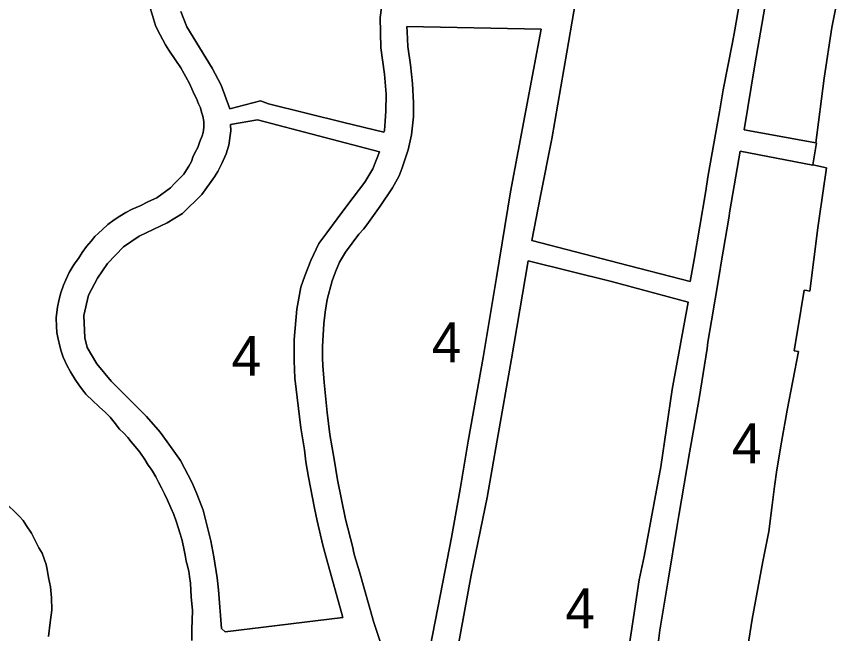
# Model space of a CAD drawing. Extents: x 598968 to 613553, y 4409678 to 4430833.
# Drawn here: x 610904.6 to 611152.7, y 4416094 to 4416279.7 of the extents above; entities that cross this region are included whole.
import ezdxf

# ---------------------------------------------------------------- set-up
doc = ezdxf.new("R2010")
doc.units = 0
doc.layers.add('1', color=7, linetype='Continuous')
doc.layers.add('ZONA 4. CASES UNIFAMILIRAS AÏLLADES EN PARCEL.LES', color=7, linetype='Continuous')

msp = doc.modelspace()

# ---------------------------------------------------------------- linework, layer by layer
at = {"layer": '1'}
for points in [[(611122.1465, 4416283.2261), (611120.8443, 4416275.6965), (611120.1666, 4416271.9363), (611117.4167, 4416257.6564), (611116.2567, 4416251.0565), (611112.8968, 4416231.9567), (611112.0195, 4416226.6664), (611108.6869, 4416206.517), (611107.4169, 4416199.977), (611086.0378, 4416205.4807), (611059.7635, 4416212.2445), (611062.3773, 4416225.6928), (611065.8373, 4416242.8526), (611070.3271, 4416269.0224), (611074.477, 4416293.5821)], [(611152.7081, 4416289.6021), (611150.0762, 4416276.3668), (611147.8011, 4416261.1727), (611145.2963, 4416241.7072), (611145.5123, 4416241.6598), (611144.3636, 4416235.0255), (611148.4575, 4416234.1782), (611148.462, 4416234.1773), (611146.2797, 4416218.9008), (611145.8798, 4416216.1015), (611143.4764, 4416197.0747), (611142.5332, 4416197.2156), (611141.7364, 4416197.3346), (611139.8278, 4416185.7171), (611138.7449, 4416179.1258), (611138.7365, 4416179.0748), (611140.0573, 4416178.8635), (611140.0635, 4416178.8624), (611136.6245, 4416161.1893), (611134.9487, 4416151.6049), (611133.4887, 4416143.2279), (611132.8409, 4416138.1859), (611132.1202, 4416132.576), (611131.1048, 4416124.6728), (611129.2758, 4416115.6243), (611126.1216, 4416098.3258), (611124.7964, 4416090.0759)], [(611015.1347, 4416286.7958), (611014.1521, 4416279.4314), (611014.1528, 4416279.4029), (611014.1521, 4416279.3983), (611014.3487, 4416270.2895), (611015.4516, 4416262.3707), (611015.9224, 4416256.3121), (611015.8442, 4416251.2356), (611015.6477, 4416248.2124), (611015.3726, 4416245.3855), (611015.1979, 4416244.8948), (611003.1665, 4416247.848), (610980.4483, 4416253.4441), (610978.1184, 4416254.304), (610968.8635, 4416251.8889), (610966.2785, 4416259.0637), (610963.5385, 4416264.2136), (610955.9187, 4416276.5833), (610954.1386, 4416281.2632)], [(610944.9886, 4416282.0114), (610946.5088, 4416276.9931), (610947.037, 4416275.6868), (610947.8401, 4416274.1826), (610949.528, 4416271.1649), (610950.5117, 4416269.5603), (610952.5788, 4416266.4934), (610954.0882, 4416264.2951), (610955.5686, 4416261.5235), (610956.6687, 4416259.5236), (610957.4232, 4416257.9484), (610958.1259, 4416256.3839), (610958.8186, 4416255.0037), (610959.4535, 4416253.4221), (610960.0286, 4416252.1737), (610960.3486, 4416250.9037), (610960.6992, 4416249.7056), (610960.9802, 4416248.0608), (610960.9802, 4416248.0278), (610960.9802, 4416246.2757), (610960.7995, 4416244.7646), (610960.5186, 4416243.7938), (610959.7957, 4416242.0768), (610959.1923, 4416240.322), (610958.2688, 4416238.6371), (610957.7447, 4416237.4055), (610957.3187, 4416236.0439), (610956.5187, 4416234.6439), (610955.8487, 4416233.5939), (610955.0187, 4416232.2939), (610953.6387, 4416230.8839), (610952.2888, 4416229.5539), (610950.9627, 4416228.0904), (610946.8549, 4416225.1727), (610944.3817, 4416224.0145), (610941.8389, 4416222.6938), (610939.4983, 4416221.6852), (610937.5459, 4416220.7017), (610935.7648, 4416219.6033), (610934.0291, 4416218.4637), (610932.1391, 4416217.1437), (610930.4919, 4416215.6001), (610929.3155, 4416214.5194), (610928.2291, 4416213.5337), (610927.1292, 4416212.0737), (610925.6692, 4416210.4337), (610924.3532, 4416208.6325), (610923.2703, 4416206.8478), (610922.3324, 4416205.5315), (610921.6992, 4416204.7037), (610920.5212, 4416202.5992), (610919.4605, 4416200.4798), (610918.7393, 4416198.8437), (610917.952, 4416196.5591), (610917.4601, 4416194.5912), (610916.9602, 4416192.2237), (610916.7395, 4416190.7002), (610916.6191, 4416189.0163), (610916.6191, 4416188.9833), (610916.6199, 4416186.3959), (610916.6199, 4416186.3628), (610916.8082, 4416184.6291), (610917.0909, 4416183.0993), (610917.761, 4416180.1011), (610918.029, 4416178.9707), (610918.6448, 4416177.2014), (610919.737, 4416174.787), (610920.8794, 4416172.7505), (610922.2802, 4416170.4248), (610923.6399, 4416168.4813), (610924.8636, 4416166.8281), (610925.4997, 4416166.0589), (610925.9461, 4416165.613), (610927.3319, 4416164.2808), (610929.6592, 4416162.1014), (610931.3492, 4416160.5615), (610932.8469, 4416159.0586), (610934.0292, 4416157.6215), (610935.6572, 4416155.5236), (610936.9397, 4416154.298), (610938.1106, 4416153.0167), (610939.1835, 4416151.6825), (610940.3211, 4416150.2562), (610941.7264, 4416148.5627), (610943.2291, 4416146.3319), (610944.3091, 4416144.6419), (610945.0182, 4416143.7515), (610945.6032, 4416142.7907), (610946.5892, 4416141.082), (610947.3778, 4416139.5013), (610948.2795, 4416137.7842), (610949.1963, 4416135.9894), (610950.0984, 4416134.1272), (610951.1268, 4416131.7765), (610951.9728, 4416129.8295), (610952.8054, 4416127.5168), (610953.8905, 4416123.9502), (610954.5105, 4416121.9374), (610955.1454, 4416119.0299), (610955.3568, 4416117.5801), (610955.7515, 4416115.7867), (610955.9347, 4416115.0266), (610956.4705, 4416112.7539), (610956.7382, 4416111.1351), (610956.9927, 4416109.1003), (610957.2608, 4416104.9844), (610957.5708, 4416100.9311), (610957.4469, 4416095.2132), (610957.3662, 4416091.8164)], [(611097.8675, 4416091.7255), (611098.3473, 4416094.9907), (611100.9371, 4416110.6152), (611103.407, 4416125.915), (611104.027, 4416129.525), (611107.287, 4416148.3547), (611110.1069, 4416164.7546), (611112.5245, 4416179.7333), (611112.7206, 4416181.6279), (611113.8927, 4416188.1256), (611115.9988, 4416200.5446), (611117.0653, 4416207.3976), (611117.385, 4416209.0743), (611119.091, 4416219.0271), (611119.4107, 4416221.183), (611122.5031, 4416239.1318), (611144.3404, 4416234.964), (611144.3636, 4416235.0255), (611145.5123, 4416241.6598), (611145.2963, 4416241.7072), (611123.6561, 4416245.6391), (611126.9333, 4416265.1438), (611129.931, 4416282.5068)], [(611016.3828, 4416084.7543), (611012.2518, 4416097.2903), (611007.8794, 4416112.4803), (611006.3971, 4416117.4883), (611006.0904, 4416118.7905), (611005.8348, 4416119.8373), (611003.6918, 4416128.3804), (611001.2197, 4416140.2281), (611000.2379, 4416146.448), (610999.6927, 4416149.8759), (610998.966, 4416153.9056), (610998.1304, 4416160.4855), (610997.2222, 4416169.5721), (610996.8231, 4416174.6028), (610996.7867, 4416176.781), (610996.7146, 4416180.3867), (610996.7142, 4416180.4114), (610997.1147, 4416187.2423), (610997.5523, 4416190.6726), (610998.1721, 4416194.5333), (610999.6983, 4416200.1241), (611000.7157, 4416202.883), (611001.9189, 4416205.766), (611003.6994, 4416208.7793), (611007.6645, 4416214.1633), (611009.1089, 4416215.6583), (611010.078, 4416216.9551), (611014.128, 4416222.6351), (611017.8029, 4416228.0951), (611019.8144, 4416231.7556), (611020.7335, 4416234.143), (611022.5751, 4416239.5291), (611023.5861, 4416244.1204), (611024.1375, 4416249.492), (611024.1395, 4416253.7395), (611024.1395, 4416253.7725), (611023.8658, 4416259.5739), (611023.2259, 4416265.1419), (611022.4906, 4416270.6972), (611022.2148, 4416275.0587), (611022.1699, 4416276.7255), (611062.5626, 4416275.9507), (611053.3833, 4416226.9164), (611049.0954, 4416201.1785), (611045.1718, 4416177.1058), (611040.5813, 4416151.8625), (611038.2042, 4416137.3883), (611035.638, 4416122.8969), (611032.945, 4416109.3755), (611029.1361, 4416089.805)], [(611037.3188, 4416088.5158), (611041.4857, 4416111.5126), (611046.3477, 4416134.8939), (611049.3377, 4416152.1236), (611053.6075, 4416176.7034), (611057.7974, 4416200.8531), (611058.7175, 4416206.1531), (611083.7571, 4416199.9636), (611106.8796, 4416193.7418), (611102.0267, 4416167.4123), (611098.657, 4416144.1277), (611094.4232, 4416121.4989), (611093.5561, 4416117.1088), (611092.1134, 4416110.1426), (611090.38, 4416098.7781), (611088.7436, 4416088.193)], [(610914.2934, 4416093.0549), (610914.7818, 4416097.289), (610915.2483, 4416101.0234), (610915.2474, 4416101.0494), (610915.2483, 4416101.0565), (610915.1227, 4416104.7186), (610914.8355, 4416108.0579), (610914.2436, 4416110.8711), (610913.8479, 4416113.2442), (610913.543, 4416114.6955), (610912.3222, 4416118.145), (610911.3896, 4416119.7934), (610909.1481, 4416124.1543), (610907.655, 4416126.342), (610906.6517, 4416127.946), (610905.5334, 4416129.235), (610900.8315, 4416133.8465)]]:
    msp.add_lwpolyline(points, dxfattribs=at)
msp.add_lwpolyline([(611002.8316, 4416098.7918), (610967.4717, 4416094.4961), (610966.3677, 4416095.5051), (610965.4269, 4416107.103), (610965.0036, 4416110.7433), (610964.0632, 4416117.0631), (610963.17, 4416121.861), (610960.7877, 4416131.0548), (610958.8942, 4416135.9918), (610957.5062, 4416139.2727), (610953.9631, 4416146.039), (610949.9698, 4416151.704), (610947.8535, 4416154.6152), (610943.7223, 4416159.3408), (610942.0877, 4416161.0234), (610933.1102, 4416169.9663), (610928.7871, 4416175.1939), (610925.952, 4416180.0798), (610925.1556, 4416182.9363), (610924.864, 4416189.7219), (610924.8628, 4416189.75), (610926.3502, 4416195.8591), (610929.0423, 4416200.9614), (610932.0094, 4416205.3125), (610936.88, 4416210.4141), (610941.5501, 4416213.5631), (610949.9472, 4416217.612), (610954.6201, 4416220.4397), (610960.3839, 4416226.1369), (610964.2491, 4416231.412), (610965.2016, 4416233.0937), (610966.4386, 4416235.474), (610967.774, 4416238.4233), (610968.5191, 4416240.9716), (610969.1199, 4416245.2817), (610969.099, 4416247.1694), (610977.1573, 4416248.5794), (611013.9124, 4416238.9693), (611011.948, 4416233.8649), (611009.4541, 4416229.8593), (611005.9885, 4416225.1982), (611002.6172, 4416220.7409), (611001.1842, 4416218.8098), (610998.0185, 4416214.6148), (610995.6177, 4416211.3463), (610993.2184, 4416206.2524), (610991.417, 4416201.6723), (610990.2506, 4416198.243), (610989.0176, 4416191.5833), (610988.2589, 4416182.508), (610988.2588, 4416182.4749), (610988.2421, 4416176.1082), (610988.2421, 4416176.0762), (610988.4399, 4416170.7976), (610990.2301, 4416155.9193), (610991.3538, 4416149.3073), (610991.708, 4416145.6019), (610992.5836, 4416141.0304), (610994.3134, 4416131.6733), (610995.1265, 4416127.8549), (610996.8992, 4416120.5299), (610998.0245, 4416116.1378)], close=True, dxfattribs=at)
at = {"layer": 'ZONA 4. CASES UNIFAMILIRAS AÏLLADES EN PARCEL.LES'}
for points in [[(611074.477, 4416293.5821), (611070.3271, 4416269.0224), (611065.8373, 4416242.8526), (611062.3773, 4416225.6928), (611059.7635, 4416212.2445), (611086.0378, 4416205.4807), (611107.4169, 4416199.977), (611108.6869, 4416206.517), (611112.0195, 4416226.6664), (611112.8968, 4416231.9567), (611116.2567, 4416251.0565), (611117.4167, 4416257.6564), (611120.1666, 4416271.9363), (611120.8443, 4416275.6965), (611122.1465, 4416283.2261)], [(611129.931, 4416282.5068), (611126.9333, 4416265.1438), (611123.6561, 4416245.6391), (611145.2963, 4416241.7072), (611147.8011, 4416261.1727), (611150.0762, 4416276.3668), (611152.7081, 4416289.6021)], [(610954.1386, 4416281.2632), (610955.9187, 4416276.5833), (610963.5385, 4416264.2136), (610966.2785, 4416259.0637), (610968.8635, 4416251.8889), (610978.1184, 4416254.304), (610980.4483, 4416253.4441), (611003.1665, 4416247.848), (611015.1979, 4416244.8948), (611015.3726, 4416245.3855), (611015.6477, 4416248.2124), (611015.8442, 4416251.2356), (611015.9224, 4416256.3121), (611015.4516, 4416262.3707), (611014.3487, 4416270.2895), (611014.1521, 4416279.3983), (611014.1528, 4416279.4029), (611014.1521, 4416279.4314), (611015.1347, 4416286.7958)], [(610957.3662, 4416091.8164), (610957.4469, 4416095.2132), (610957.5708, 4416100.9311), (610957.2608, 4416104.9844), (610956.9927, 4416109.1003), (610956.7382, 4416111.1351), (610956.4705, 4416112.7539), (610955.9347, 4416115.0266), (610955.7515, 4416115.7867), (610955.3568, 4416117.5801), (610955.1454, 4416119.0299), (610954.5105, 4416121.9374), (610953.8905, 4416123.9502), (610952.8054, 4416127.5168), (610951.9728, 4416129.8295), (610951.1268, 4416131.7765), (610950.0984, 4416134.1272), (610949.1963, 4416135.9894), (610948.2795, 4416137.7842), (610947.3778, 4416139.5013), (610946.5892, 4416141.082), (610945.6032, 4416142.7907), (610945.0182, 4416143.7515), (610944.3091, 4416144.6419), (610943.2291, 4416146.3319), (610941.7264, 4416148.5627), (610940.3211, 4416150.2562), (610939.1835, 4416151.6825), (610938.1106, 4416153.0167), (610936.9397, 4416154.298), (610935.6572, 4416155.5236), (610934.0292, 4416157.6215), (610932.8469, 4416159.0586), (610931.3492, 4416160.5615), (610929.6592, 4416162.1014), (610927.3319, 4416164.2808), (610925.9461, 4416165.613), (610925.4997, 4416166.0589), (610924.8636, 4416166.8281), (610923.6399, 4416168.4813), (610922.2802, 4416170.4248), (610920.8794, 4416172.7505), (610919.737, 4416174.787), (610918.6448, 4416177.2014), (610918.029, 4416178.9707), (610917.761, 4416180.1011), (610917.0909, 4416183.0993), (610916.8082, 4416184.6291), (610916.6199, 4416186.3628), (610916.6199, 4416186.3959), (610916.6191, 4416188.9833), (610916.6191, 4416189.0163), (610916.7395, 4416190.7002), (610916.9602, 4416192.2237), (610917.4601, 4416194.5912), (610917.952, 4416196.5591), (610918.7393, 4416198.8437), (610919.4605, 4416200.4798), (610920.5212, 4416202.5992), (610921.6992, 4416204.7037), (610922.3324, 4416205.5315), (610923.2703, 4416206.8478), (610924.3532, 4416208.6325), (610925.6692, 4416210.4337), (610927.1292, 4416212.0737), (610928.2291, 4416213.5337), (610929.3155, 4416214.5194), (610930.4919, 4416215.6001), (610932.1391, 4416217.1437), (610934.0291, 4416218.4637), (610935.7648, 4416219.6033), (610937.5459, 4416220.7017), (610939.4983, 4416221.6852), (610941.8389, 4416222.6938), (610944.3817, 4416224.0145), (610946.8549, 4416225.1727), (610950.9627, 4416228.0904), (610952.2888, 4416229.5539), (610953.6387, 4416230.8839), (610955.0187, 4416232.2939), (610955.8487, 4416233.5939), (610956.5187, 4416234.6439), (610957.3187, 4416236.0439), (610957.7447, 4416237.4055), (610958.2688, 4416238.6371), (610959.1923, 4416240.322), (610959.7957, 4416242.0768), (610960.5186, 4416243.7938), (610960.7995, 4416244.7646), (610960.9802, 4416246.2757), (610960.9802, 4416248.0278), (610960.9802, 4416248.0608), (610960.6992, 4416249.7056), (610960.3486, 4416250.9037), (610960.0286, 4416252.1737), (610959.4535, 4416253.4221), (610958.8186, 4416255.0037), (610958.1259, 4416256.3839), (610957.4232, 4416257.9484), (610956.6687, 4416259.5236), (610955.5686, 4416261.5235), (610954.0882, 4416264.2951), (610952.5788, 4416266.4934), (610950.5117, 4416269.5603), (610949.528, 4416271.1649), (610947.8401, 4416274.1826), (610947.037, 4416275.6868), (610946.5088, 4416276.9931), (610944.9886, 4416282.0114)], [(611029.1361, 4416089.805), (611032.945, 4416109.3755), (611035.638, 4416122.8969), (611038.2042, 4416137.3883), (611040.5813, 4416151.8625), (611045.1718, 4416177.1058), (611049.0954, 4416201.1785), (611053.3833, 4416226.9164), (611062.5626, 4416275.9507), (611022.1699, 4416276.7255), (611022.2148, 4416275.0587), (611022.4906, 4416270.6972), (611023.2259, 4416265.1419), (611023.8658, 4416259.5739), (611024.1395, 4416253.7725), (611024.1395, 4416253.7395), (611024.1375, 4416249.492), (611023.5861, 4416244.1204), (611022.5751, 4416239.5291), (611020.7335, 4416234.143), (611019.8144, 4416231.7556), (611017.8029, 4416228.0951), (611014.128, 4416222.6351), (611010.078, 4416216.9551), (611009.1089, 4416215.6583), (611007.6645, 4416214.1633), (611003.6994, 4416208.7793), (611001.9189, 4416205.766), (611000.7157, 4416202.883), (610999.6983, 4416200.1241), (610998.1721, 4416194.5333), (610997.5523, 4416190.6726), (610997.1147, 4416187.2423), (610996.7142, 4416180.4114), (610996.7146, 4416180.3867), (610996.7867, 4416176.781), (610996.8231, 4416174.6028), (610997.2222, 4416169.5721), (610998.1304, 4416160.4855), (610998.966, 4416153.9056), (610999.6927, 4416149.8759), (611000.2379, 4416146.448), (611001.2197, 4416140.2281), (611003.6918, 4416128.3804), (611005.8348, 4416119.8373), (611006.0904, 4416118.7905), (611006.3971, 4416117.4883), (611007.8794, 4416112.4803), (611012.2518, 4416097.2903), (611016.3828, 4416084.7543)], [(611124.7964, 4416090.0759), (611126.1216, 4416098.3258), (611129.2758, 4416115.6243), (611131.1048, 4416124.6728), (611132.1202, 4416132.576), (611132.8409, 4416138.1859), (611133.4887, 4416143.2279), (611134.9487, 4416151.6049), (611136.6245, 4416161.1893), (611140.0635, 4416178.8624), (611140.0573, 4416178.8635), (611138.7365, 4416179.0748), (611138.7449, 4416179.1258), (611139.8278, 4416185.7171), (611141.7364, 4416197.3346), (611142.5332, 4416197.2156), (611143.4764, 4416197.0747), (611145.8798, 4416216.1015), (611146.2797, 4416218.9008), (611148.462, 4416234.1773), (611148.4575, 4416234.1782), (611144.3636, 4416235.0255), (611144.3404, 4416234.964), (611122.5031, 4416239.1318), (611119.4107, 4416221.183), (611119.091, 4416219.0271), (611117.385, 4416209.0743), (611117.0653, 4416207.3976), (611115.9988, 4416200.5446), (611113.8927, 4416188.1256), (611112.7206, 4416181.6279), (611112.5245, 4416179.7333), (611110.1069, 4416164.7546), (611107.287, 4416148.3547), (611104.027, 4416129.525), (611103.407, 4416125.915), (611100.9371, 4416110.6152), (611098.3473, 4416094.9907), (611097.8675, 4416091.7255)], [(611088.7436, 4416088.193), (611090.38, 4416098.7781), (611092.1134, 4416110.1426), (611093.5561, 4416117.1088), (611094.4232, 4416121.4989), (611098.657, 4416144.1277), (611102.0267, 4416167.4123), (611106.8796, 4416193.7418), (611083.7571, 4416199.9636), (611058.7175, 4416206.1531), (611057.7974, 4416200.8531), (611053.6075, 4416176.7034), (611049.3377, 4416152.1236), (611046.3477, 4416134.8939), (611041.4857, 4416111.5126), (611037.3188, 4416088.5158)], [(610900.8315, 4416133.8465), (610905.5334, 4416129.235), (610906.6517, 4416127.946), (610907.655, 4416126.342), (610909.1481, 4416124.1543), (610911.3896, 4416119.7934), (610912.3222, 4416118.145), (610913.543, 4416114.6955), (610913.8479, 4416113.2442), (610914.2436, 4416110.8711), (610914.8355, 4416108.0579), (610915.1227, 4416104.7186), (610915.2483, 4416101.0565), (610915.2474, 4416101.0494), (610915.2483, 4416101.0234), (610914.7818, 4416097.289), (610914.2934, 4416093.0549)]]:
    msp.add_lwpolyline(points, dxfattribs=at)
msp.add_lwpolyline([(611002.8316, 4416098.7918), (610998.0245, 4416116.1378), (610996.8992, 4416120.5299), (610995.1265, 4416127.8549), (610994.3134, 4416131.6733), (610992.5836, 4416141.0304), (610991.708, 4416145.6019), (610991.3538, 4416149.3073), (610990.2301, 4416155.9193), (610988.4399, 4416170.7976), (610988.2421, 4416176.0762), (610988.2421, 4416176.1082), (610988.2588, 4416182.4749), (610988.2589, 4416182.508), (610989.0176, 4416191.5833), (610990.2506, 4416198.243), (610991.417, 4416201.6723), (610993.2184, 4416206.2524), (610995.6177, 4416211.3463), (610998.0185, 4416214.6148), (611001.1842, 4416218.8098), (611002.6172, 4416220.7409), (611005.9885, 4416225.1982), (611009.4541, 4416229.8593), (611011.948, 4416233.8649), (611013.9124, 4416238.9693), (610977.1573, 4416248.5794), (610969.099, 4416247.1694), (610969.1199, 4416245.2817), (610968.5191, 4416240.9716), (610967.774, 4416238.4233), (610966.4386, 4416235.474), (610965.2016, 4416233.0937), (610964.2491, 4416231.412), (610960.3839, 4416226.1369), (610954.6201, 4416220.4397), (610949.9472, 4416217.612), (610941.5501, 4416213.5631), (610936.88, 4416210.4141), (610932.0094, 4416205.3125), (610929.0423, 4416200.9614), (610926.3502, 4416195.8591), (610924.8628, 4416189.75), (610924.864, 4416189.7219), (610925.1556, 4416182.9363), (610925.952, 4416180.0798), (610928.7871, 4416175.1939), (610933.1102, 4416169.9663), (610942.0877, 4416161.0234), (610943.7223, 4416159.3408), (610947.8535, 4416154.6152), (610949.9698, 4416151.704), (610953.9631, 4416146.039), (610957.5062, 4416139.2727), (610958.8942, 4416135.9918), (610960.7877, 4416131.0548), (610963.17, 4416121.861), (610964.0632, 4416117.0631), (610965.0036, 4416110.7433), (610965.4269, 4416107.103), (610966.3677, 4416095.5051), (610967.4717, 4416094.4961)], close=True, dxfattribs=at)

# ---------------------------------------------------------------- texts
for p in [(611029.6384, 4416175.6508), (610969.3876, 4416171.5377), (611120.0109, 4416145.2075), (611069.8491, 4416095.5393)]:
    msp.add_text('4', height=12, dxfattribs=at).set_placement(p)

doc.saveas('drawing.dxf')
